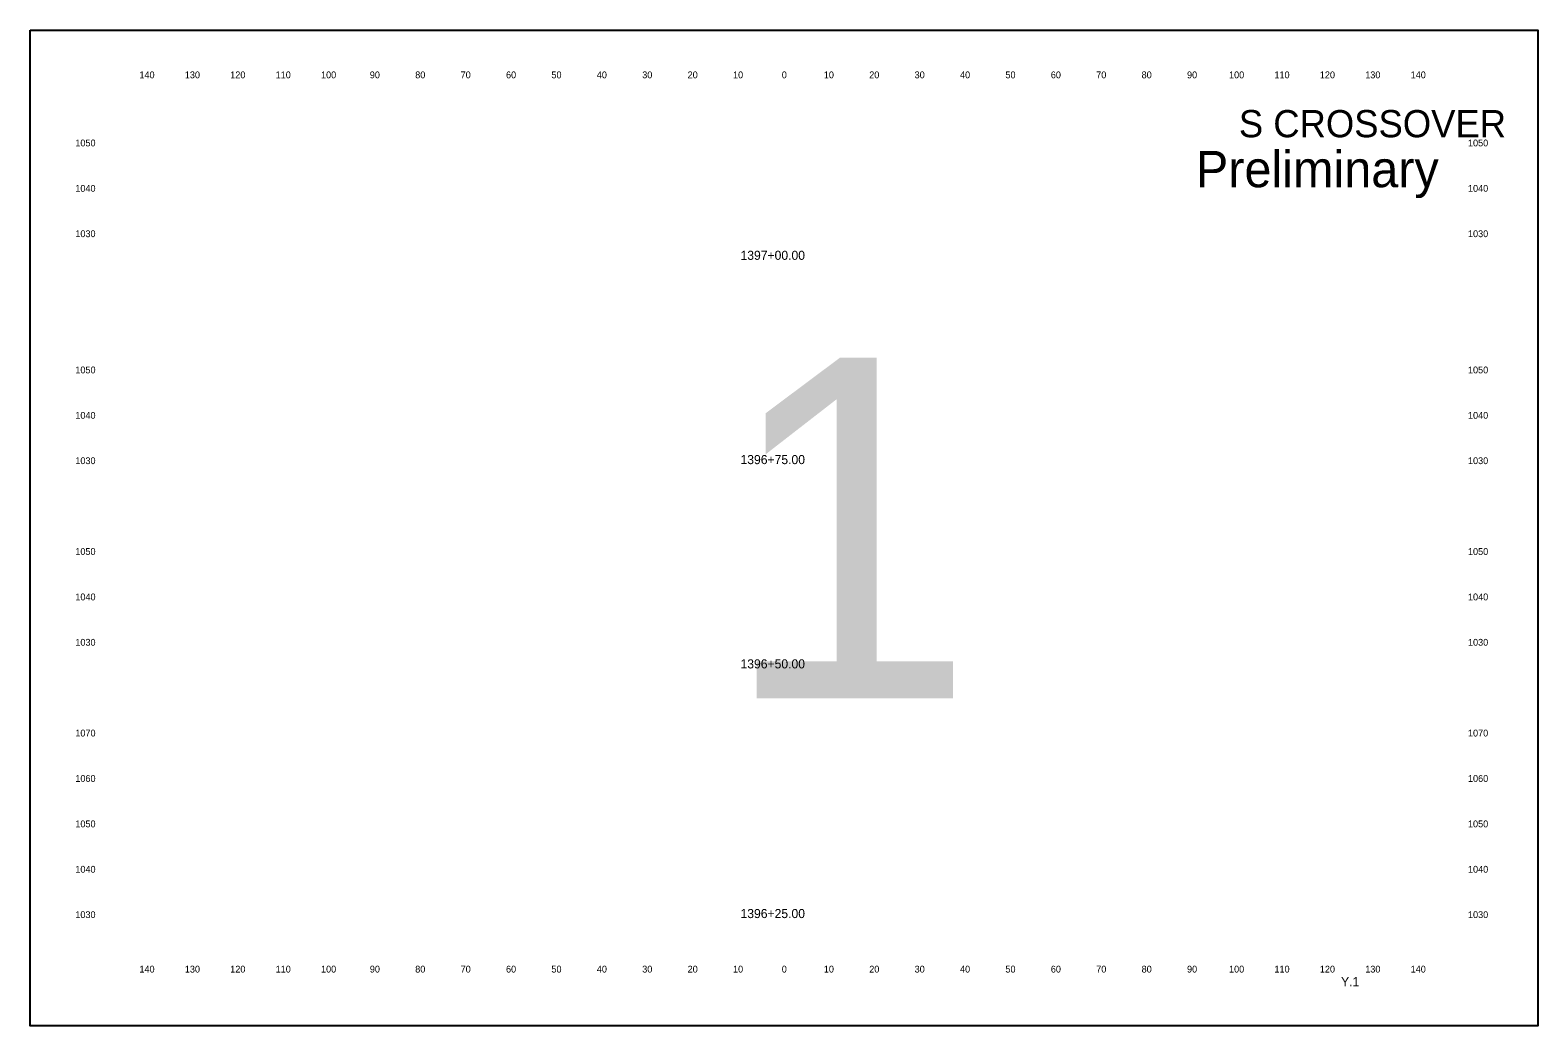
# Model space of a CAD drawing. Extents: x 10123 to 14768, y 9730 to 9950.
# Drawn here: x 10123.2 to 10455.3, y 9730.3 to 9949.6 of the extents above; entities that cross this region are included whole.
import ezdxf

# ---------------------------------------------------------------- set-up
doc = ezdxf.new("R2010")
doc.units = 0
for name, color, linetype in [('dsnTextCpn', 7, 'Continuous'), ('dsnTextCpnTitleSheetLocDesc', 7, 'Continuous'), ('dsnTextCpnTitleSheetPIN', 7, 'Continuous'), ('dsnTextCpnTitleSheetWorkType', 7, 'Continuous')]:
    doc.layers.add(name, color=color, linetype=linetype)

msp = doc.modelspace()

# ---------------------------------------------------------------- linework, layer by layer
at = {"layer": 'dsnTextCpnTitleSheetWorkType'}
msp.add_lwpolyline([(10123.21, 9949.6), (10455.29, 9949.6), (10455.29, 9730.26), (10123.21, 9730.26)], close=True, dxfattribs=at)

# ---------------------------------------------------------------- texts
at = {"layer": 'dsnTextCpn'}
for s, height, p in [('140', 1.5, (10147.27, 9939)), ('130', 1.5, (10157.27, 9939)), ('120', 1.5, (10167.27, 9939)), ('110', 1.5, (10177.27, 9939)), ('100', 1.5, (10187.27, 9939)), ('90', 1.5, (10198.02, 9939)), ('80', 1.5, (10208.02, 9939)), ('70', 1.5, (10218.02, 9939)), ('60', 1.5, (10228.02, 9939)), ('50', 1.5, (10238.02, 9939)), ('40', 1.5, (10248.02, 9939)), ('30', 1.5, (10258.02, 9939)), ('20', 1.5, (10268.02, 9939)), ('10', 1.5, (10278.02, 9939)), ('0', 1.5, (10288.76, 9939)), ('0', 1.5, (10288.76, 9939)), ('10', 1.5, (10298.02, 9939)), ('20', 1.5, (10308.02, 9939)), ('30', 1.5, (10318.02, 9939)), ('40', 1.5, (10328.02, 9939)), ('50', 1.5, (10338.02, 9939)), ('60', 1.5, (10348.02, 9939)), ('70', 1.5, (10358.02, 9939)), ('80', 1.5, (10368.02, 9939)), ('90', 1.5, (10378.02, 9939)), ('100', 1.5, (10387.27, 9939)), ('110', 1.5, (10397.27, 9939)), ('120', 1.5, (10407.27, 9939)), ('130', 1.5, (10417.27, 9939)), ('140', 1.5, (10427.27, 9939)), ('S CROSSOVER', 6, (10389.44, 9926)), ('1050', 1.5, (10133.15, 9924)), ('1050', 1.5, (10439.9, 9924)), ('1040', 1.5, (10133.15, 9914)), ('1040', 1.5, (10439.9, 9914)), ('1030', 1.5, (10133.15, 9904)), ('1030', 1.5, (10439.9, 9904)), ('1397+00.00', 2, (10279.67, 9899)), ('1050', 1.5, (10133.15, 9874)), ('1050', 1.5, (10439.9, 9874)), ('1040', 1.5, (10133.15, 9864)), ('1040', 1.5, (10439.9, 9864)), ('1030', 1.5, (10133.15, 9854)), ('1396+75.00', 2, (10279.67, 9854)), ('1030', 1.5, (10439.9, 9854)), ('1050', 1.5, (10133.15, 9834)), ('1050', 1.5, (10439.9, 9834)), ('1040', 1.5, (10133.15, 9824)), ('1040', 1.5, (10439.9, 9824)), ('1030', 1.5, (10133.15, 9814)), ('1030', 1.5, (10439.9, 9814)), ('1396+50.00', 2, (10279.67, 9809)), ('1070', 1.5, (10133.15, 9794)), ('1070', 1.5, (10439.9, 9794)), ('1060', 1.5, (10133.15, 9784)), ('1060', 1.5, (10439.9, 9784)), ('1050', 1.5, (10133.15, 9774)), ('1050', 1.5, (10439.9, 9774)), ('1040', 1.5, (10133.15, 9764)), ('1040', 1.5, (10439.9, 9764)), ('1030', 1.5, (10133.15, 9754)), ('1396+25.00', 2, (10279.67, 9754)), ('1030', 1.5, (10439.9, 9754)), ('140', 1.5, (10147.27, 9742)), ('130', 1.5, (10157.27, 9742)), ('120', 1.5, (10167.27, 9742)), ('110', 1.5, (10177.27, 9742)), ('100', 1.5, (10187.27, 9742)), ('90', 1.5, (10198.02, 9742)), ('80', 1.5, (10208.02, 9742)), ('70', 1.5, (10218.02, 9742)), ('60', 1.5, (10228.02, 9742)), ('50', 1.5, (10238.02, 9742)), ('40', 1.5, (10248.02, 9742)), ('30', 1.5, (10258.02, 9742)), ('20', 1.5, (10268.02, 9742)), ('10', 1.5, (10278.02, 9742)), ('0', 1.5, (10288.76, 9742)), ('0', 1.5, (10288.76, 9742)), ('10', 1.5, (10298.02, 9742)), ('20', 1.5, (10308.02, 9742)), ('30', 1.5, (10318.02, 9742)), ('40', 1.5, (10328.02, 9742)), ('50', 1.5, (10338.02, 9742)), ('60', 1.5, (10348.02, 9742)), ('70', 1.5, (10358.02, 9742)), ('80', 1.5, (10368.02, 9742)), ('90', 1.5, (10378.02, 9742)), ('100', 1.5, (10387.27, 9742)), ('110', 1.5, (10397.27, 9742)), ('120', 1.5, (10407.27, 9742)), ('130', 1.5, (10417.27, 9742)), ('140', 1.5, (10427.27, 9742))]:
    msp.add_text(s, height=height, dxfattribs=at).set_placement(p)
at = {"layer": 'dsnTextCpnTitleSheetLocDesc'}
msp.add_text('Preliminary', height=8, dxfattribs=at).set_placement((10379.97, 9915))
at = {"layer": 'dsnTextCpnTitleSheetPIN'}
msp.add_text('Y.1', height=2, dxfattribs=at).set_placement((10411.95, 9739))
at = {"layer": 'dsnTextCpnTitleSheetWorkType'}
msp.add_text('1', height=75, dxfattribs=at).set_placement((10275.6, 9802.43))

doc.saveas('drawing.dxf')
